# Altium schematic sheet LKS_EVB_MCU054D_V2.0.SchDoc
size A4; SheetNumber: 1; SheetTotal: 1
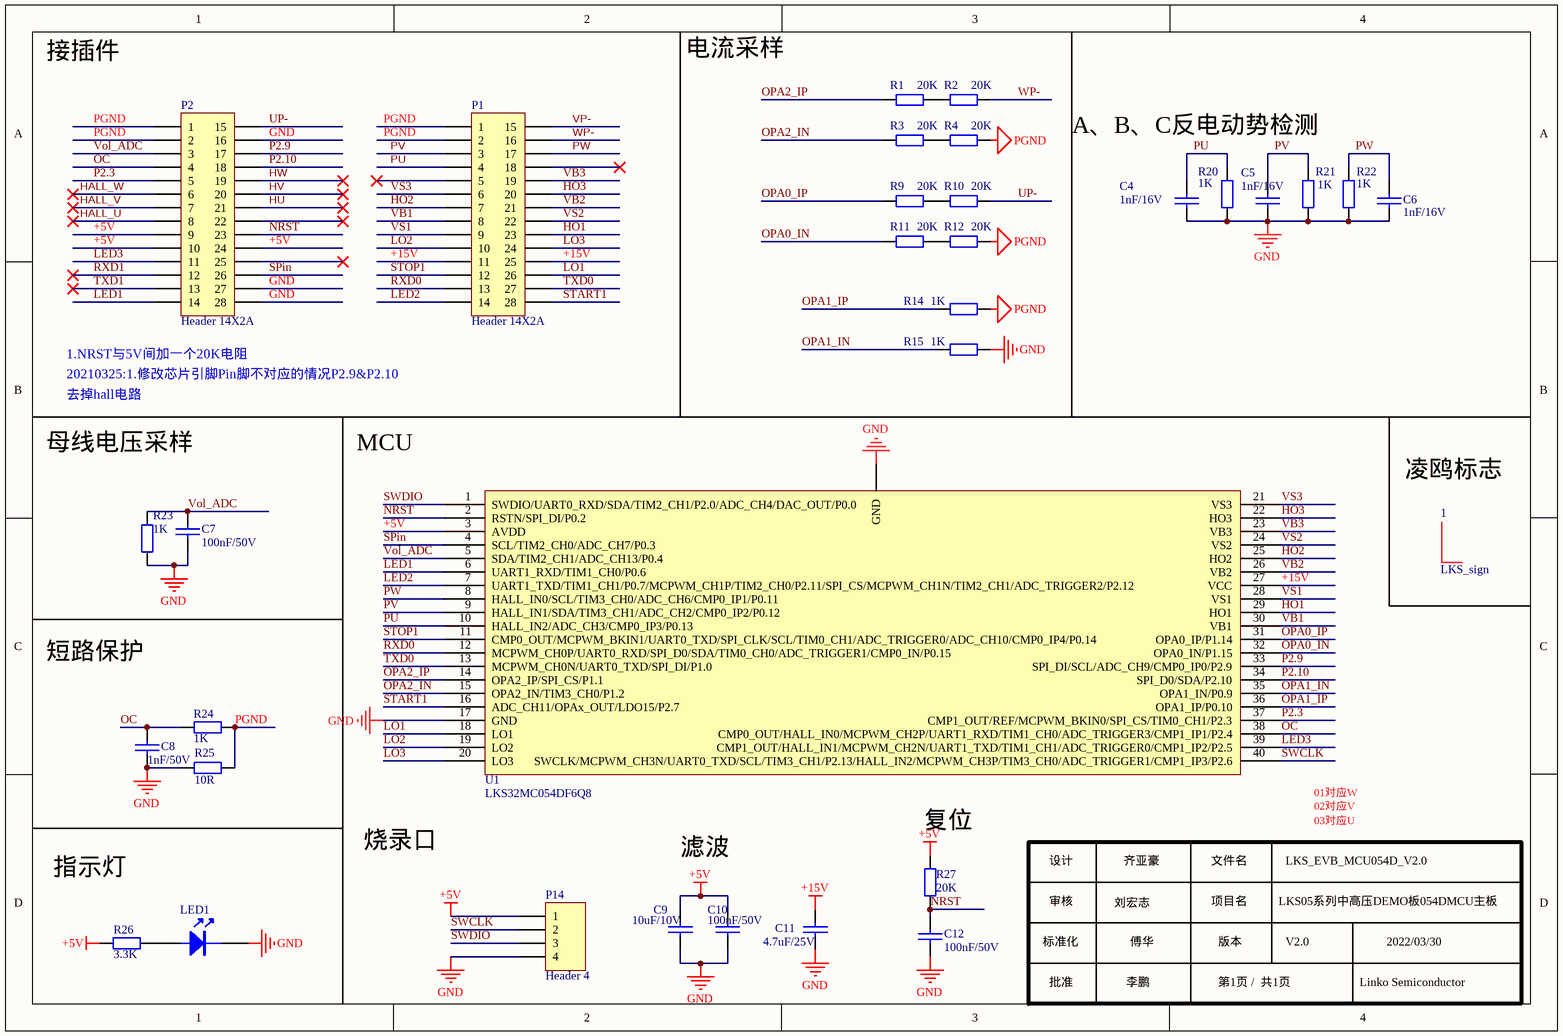
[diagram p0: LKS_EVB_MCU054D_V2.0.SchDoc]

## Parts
1  LKS_sign  [LKS_LOGO2]
C4  1nF/16V  [0603C]
C5  1nF/16V  [0603C]
C6  1nF/16V  [0603C]
C7  100nF/50V  [0603C]
C8  1nF/50V  [0603C]
C9  10uF/10V  [0603C]
C10  100nF/50V  [0603C]
C11  4.7uF/25V  [0603C]
C12  100nF/50V  [0603C]
LED1  LED  [LED 0603R]  (value not drawn)
P1  Header 14X2A  [HDR2X14_CEN]
P2  Header 14X2A  [HDR2X14_CEN]
P14  Header 4  [HDR1X4]
R1  20K  [0603R]
R2  20K  [0603R]
R3  20K  [0603R]
R4  20K  [0603R]
R9  20K  [0603R]
R10  20K  [0603R]
R11  20K  [0603R]
R12  20K  [0603R]
R14  1K  [0603R]
R15  1K  [0603R]
R20  1K  [0603R]
R21  1K  [0603R]
R22  1K  [0603R]
R23  1K  [0603R]
R24  1K  [0603R]
R25  10R  [0603R]
R26  3.3K  [0603R]
R27  20K  [0603R]
U1  LKS32MC054DF6Q8  [QFN40]

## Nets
+5V: C9.2 C10.2 P2.9 P2.10 P2.24 P14.1 R26.2 R27.1 U1.3(AVDD)
+15V: C11.2 P1.11 P1.25 U1.27(VCC)
GND: C4.2 C5.2 C6.2 C7.1 C8.1 C9.1 C10.1 C11.1 C12.2 LED1.2(K) P2.16 P2.27 P2.28 P14.4 R15.1 R20.2 R21.2 R22.2 R23.1 R25.2 U1.0(GND) U1.17(GND)
PGND: P1.1 P1.2 P2.1 P2.2 R4.1 R12.1 R14.1 R24.2 R25.1
HALL_U: P2.8
HALL_V: P2.7
HALL_W: P2.6
HO1: P1.23 U1.29(HO1)
HO2: P1.7 U1.25(HO2)
HO3: P1.20 U1.22(HO3)
HU: P2.21
HV: P2.20
HW: P2.19
LED1: P2.14 U1.6(UART1_RXD/TIM1_CH0/P0.6)
LED2: P1.14 U1.7(UART1_TXD/TIM1_CH1/P0.7/MCPWM_CH1P/TIM2_CH0/P2.11/SPI_CS/MCPWM_CH1N/TIM2_CH1/ADC_TRIGGER2/P2.12)
LED3: P2.11 U1.39(CMP1_OUT/HALL_IN1/MCPWM_CH2N/UART1_TXD/TIM1_CH1/ADC_TRIGGER0/CMP1_IP2/P2.5)
LO1: P1.26 U1.18(LO1)
LO2: P1.10 U1.19(LO2)
LO3: P1.24 U1.20(LO3)
NRST: C12.1 P2.23 R27.2 U1.2(RSTN/SPI_DI/P0.2)
OC: C8.2 P2.4 R24.1 U1.38(CMP0_OUT/HALL_IN0/MCPWM_CH2P/UART1_RXD/TIM1_CH0/ADC_TRIGGER3/CMP1_IP1/P2.4)
OPA0_IN: R11.2 U1.32(OPA0_IN/P1.15)
OPA0_IP: R9.2 U1.31(OPA0_IP/P1.14)
OPA1_IN: R15.2 U1.35(OPA1_IN/P0.9)
OPA1_IP: R14.2 U1.36(OPA1_IP/P0.10)
OPA2_IN: R3.2 U1.15(OPA2_IN/TIM3_CH0/P1.2)
OPA2_IP: R1.2 U1.14(OPA2_IP/SPI_CS/P1.1)
P2.3: P2.5 U1.37(CMP1_OUT/REF/MCPWM_BKIN0/SPI_CS/TIM0_CH1/P2.3)
P2.9: P2.17 U1.33(SPI_DI/SCL/ADC_CH9/CMP0_IP0/P2.9)
P2.10: P2.18 U1.34(SPI_D0/SDA/P2.10)
PU: C4.1 P1.4 R20.1 U1.10(HALL_IN2/ADC_CH3/CMP0_IP3/P0.13)
PV: C5.1 P1.3 R21.1 U1.9(HALL_IN1/SDA/TIM3_CH1/ADC_CH2/CMP0_IP2/P0.12)
PW: C6.1 P1.17 R22.1 U1.8(HALL_IN0/SCL/TIM3_CH0/ADC_CH6/CMP0_IP1/P0.11)
RXD0: P1.13 U1.12(MCPWM_CH0P/UART0_RXD/SPI_D0/SDA/TIM0_CH0/ADC_TRIGGER1/CMP0_IN/P0.15)
RXD1: P2.12
SPin: P2.26 U1.4(SCL/TIM2_CH0/ADC_CH7/P0.3)
START1: P1.28 U1.16(ADC_CH11/OPAx_OUT/LDO15/P2.7)
STOP1: P1.12 U1.11(CMP0_OUT/MCPWM_BKIN1/UART0_TXD/SPI_CLK/SCL/TIM0_CH1/ADC_TRIGGER0/ADC_CH10/CMP0_IP4/P0.14)
SWCLK: P14.2 U1.40(SWCLK/MCPWM_CH3N/UART0_TXD/SCL/TIM3_CH1/P2.13/HALL_IN2/MCPWM_CH3P/TIM3_CH0/ADC_TRIGGER1/CMP1_IP3/P2.6)
SWDIO: P14.3 U1.1(SWDIO/UART0_RXD/SDA/TIM2_CH1/P2.0/ADC_CH4/DAC_OUT/P0.0)
TXD0: P1.27 U1.13(MCPWM_CH0N/UART0_TXD/SPI_DI/P1.0)
TXD1: P2.13
UP-: P2.15 R10.1
VB1: P1.8 U1.30(VB1)
VB2: P1.21 U1.26(VB2)
VB3: P1.19 U1.23(VB3)
Vol_ADC: C7.2 P2.3 R23.2 U1.5(SDA/TIM2_CH1/ADC_CH13/P0.4)
VP-: P1.15
VS1: P1.9 U1.28(VS1)
VS2: P1.22 U1.24(VS2)
VS3: P1.6 U1.21(VS3)
WP-: P1.16 R2.1
NetLED1_1: LED1.1(A) R26.1
NetR1_1: R1.1 R2.2
NetR3_1: R3.1 R4.2
NetR9_1: R9.1 R10.2
NetR11_1: R11.1 R12.2

Not connected (* = marked no-connect by the designer): P1 5* 18*; P2 22* 25*

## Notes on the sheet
- 接插件
- (near P2) 1.NRST与5V间加一个20K电阻
- 20210325:1.修改芯片引脚Pin脚不对应的情况P2.9&P2.10
- 去掉hall电路
- 母线电压采样
- (near 1) 凌鸥标志
- 短路保护
- 烧录口
- 复位
- 01对应W
- 02对应V
- 03对应U
- 指示灯
- 滤波
- 设计
- 审核
- 刘宏志
- 齐亚豪
- 文件名
- 项目名
- LKS05系列中高压DEMO板054DMCU主板
- LKS_EVB_MCU054D_V2.0
- 标准化
- 批准
- 李鹏
- 傅华
- 版本
- 第1页 /  共1页
- V2.0
- Linko Semiconductor
- 2022/03/30
- Labels drawn without touching a wire or pin: A、B、C反电动势检测, MCU, 电流采样

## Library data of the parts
C4-C6 = CAP: Capacitor
C7-C12 = C: Capacitor
LED1 = LED: LED_Light
P1 P2 = Header 14X2A: Header, 14-Pin, Dual row
P14 = Header 4: Header, 4-Pin
R1-R4 R9-R12 R14 R15 R20-R25 = Res: Resistor; Value: K
R26 R27 = Res: Resistor; Value: 330
U1 = LKS32MC054DF6Q8: 芯片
